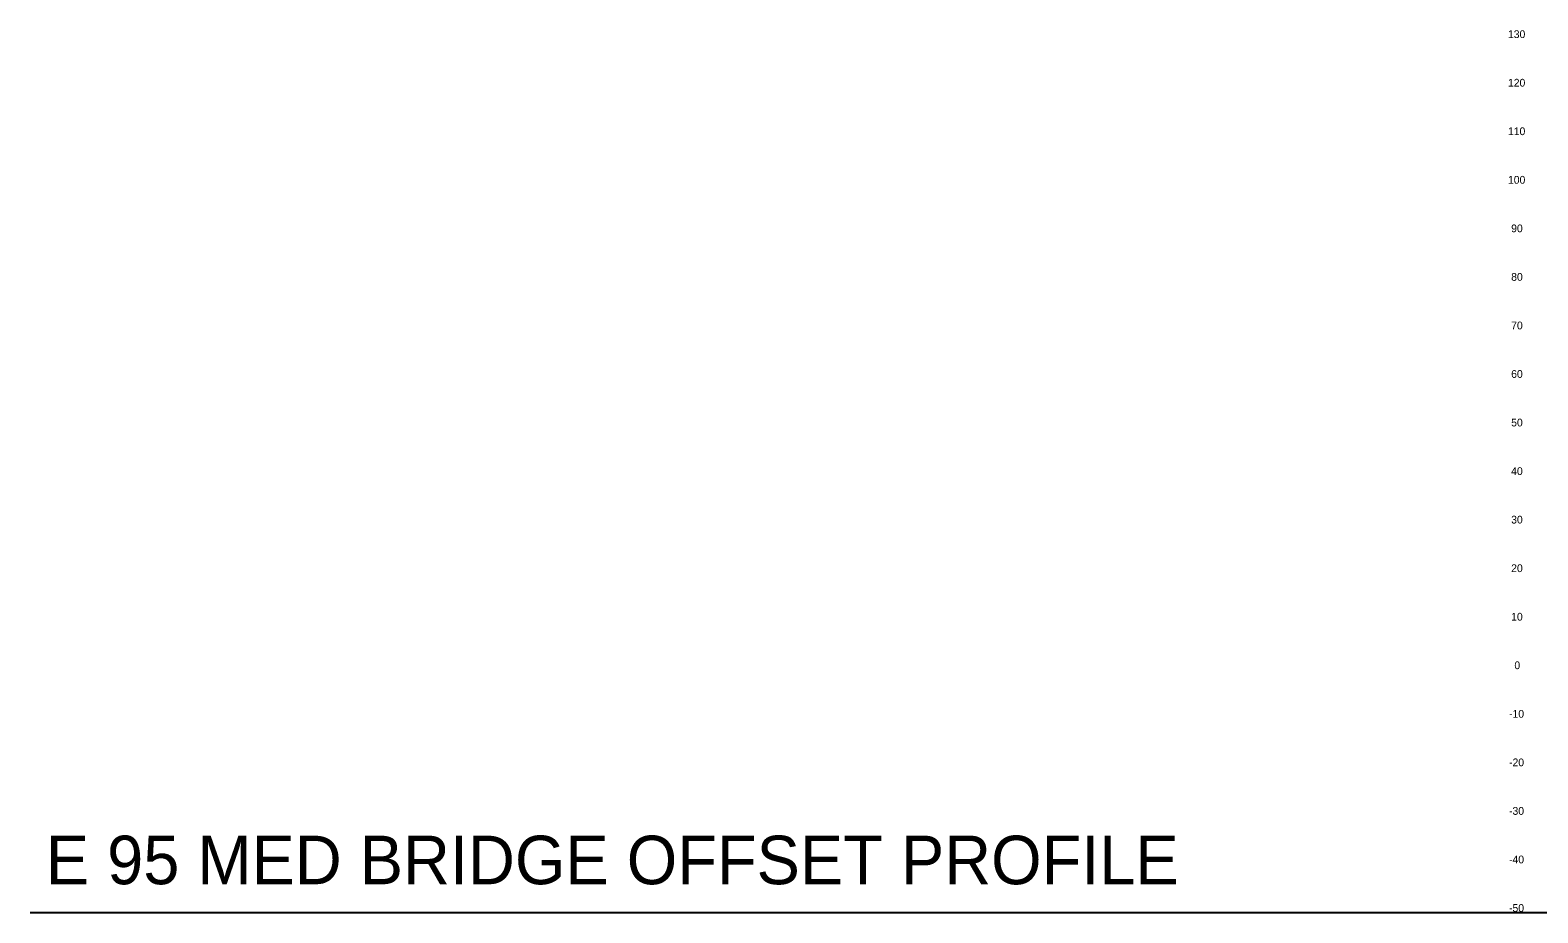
# Model space of a CAD drawing. Extents: x 2147288 to 2220488, y 740833 to 759333.
# Drawn here: x 2197288 to 2198841, y 750083 to 750993 of the extents above; entities that cross this region are included whole.
import ezdxf

# ---------------------------------------------------------------- set-up
doc = ezdxf.new("R2010")
doc.units = 0
doc.layers.add('RD_DDB_ElevTX', color=7, linetype='Continuous')
doc.layers.add('RD_GPK_Profile_Cell', color=7, linetype='Continuous')

msp = doc.modelspace()

# ---------------------------------------------------------------- linework, layer by layer
at = {"layer": 'RD_GPK_Profile_Cell'}
msp.add_line((2198888.3, 750083.4), (2197288.3, 750083.4), dxfattribs=at)

# ---------------------------------------------------------------- texts
at = {"layer": 'RD_DDB_ElevTX'}
for s, p in [('130', (2198810, 750984.4)), ('130', (2198810, 750984.4)), ('130', (2198810, 750984.4)), ('120', (2198810, 750934.4)), ('120', (2198810, 750934.4)), ('120', (2198810, 750934.4)), ('110', (2198810, 750884.4)), ('110', (2198810, 750884.4)), ('110', (2198810, 750884.4)), ('100', (2198810, 750834.4)), ('100', (2198810, 750834.4)), ('100', (2198810, 750834.4)), ('90', (2198813.3, 750784.4)), ('90', (2198813.3, 750784.4)), ('90', (2198813.3, 750784.4)), ('80', (2198813.3, 750734.4)), ('80', (2198813.3, 750734.4)), ('80', (2198813.3, 750734.4)), ('70', (2198813.3, 750684.4)), ('70', (2198813.3, 750684.4)), ('70', (2198813.3, 750684.4)), ('60', (2198813.3, 750634.4)), ('60', (2198813.3, 750634.4)), ('60', (2198813.3, 750634.4)), ('50', (2198813.3, 750584.4)), ('50', (2198813.3, 750584.4)), ('50', (2198813.3, 750584.4)), ('40', (2198813.3, 750534.4)), ('40', (2198813.3, 750534.4)), ('40', (2198813.3, 750534.4)), ('30', (2198813.3, 750484.4)), ('30', (2198813.3, 750484.4)), ('30', (2198813.3, 750484.4)), ('20', (2198813.3, 750434.4)), ('20', (2198813.3, 750434.4)), ('20', (2198813.3, 750434.4)), ('10', (2198813.3, 750384.4)), ('10', (2198813.3, 750384.4)), ('10', (2198813.3, 750384.4)), ('0', (2198816.6, 750334.4)), ('0', (2198816.6, 750334.4)), ('0', (2198816.6, 750334.4)), ('-10', (2198811.1, 750284.4)), ('-10', (2198811.1, 750284.4)), ('-10', (2198811.1, 750284.4)), ('-20', (2198811.1, 750234.4)), ('-20', (2198811.1, 750234.4)), ('-20', (2198811.1, 750234.4)), ('-30', (2198811.1, 750184.4)), ('-30', (2198811.1, 750184.4)), ('-30', (2198811.1, 750184.4)), ('-40', (2198811.1, 750134.4)), ('-40', (2198811.1, 750134.4)), ('-40', (2198811.1, 750134.4)), ('-50', (2198811.1, 750084.4)), ('-50', (2198811.1, 750084.4)), ('-50', (2198811.1, 750084.4))]:
    msp.add_text(s, height=8, dxfattribs=at).set_placement(p)
at = {"layer": 'RD_GPK_Profile_Cell'}
msp.add_text('E 95 MED BRIDGE OFFSET PROFILE', height=50, dxfattribs=at).set_placement((2197304.4, 750112.9))

doc.saveas('drawing.dxf')
